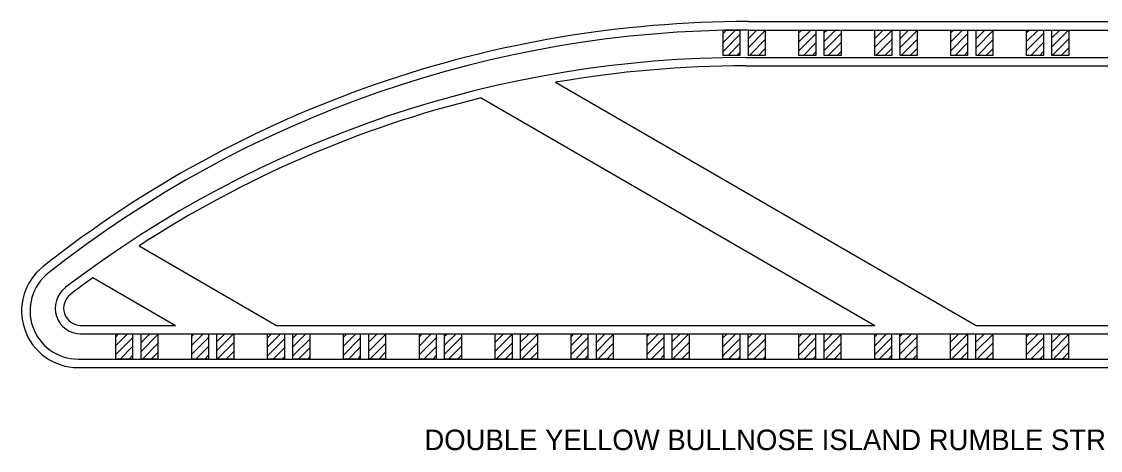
# Model space of a CAD drawing. Extents: x 49976.2 to 50021, y 49987.6 to 50011.4.
# Drawn here: x 50005.605 to 50009.802, y 49990.662 to 49992.329 of the extents above; entities that cross this region are included whole.
import ezdxf

# ---------------------------------------------------------------- set-up
doc = ezdxf.new("R2010")
doc.units = 0
doc.layers.add('Level 1', color=7, linetype='Continuous')
doc.layers.add('Level 2', color=7, linetype='Continuous')

msp = doc.modelspace()

# ---------------------------------------------------------------- linework, layer by layer
at = {"layer": 'Level 1'}
for p, q in [((50008.4327, 49992.329), (50010.6628, 49992.329)), ((50008.3343, 49992.1978), (50008.3343, 49992.2962)), ((50008.3343, 49992.2962), (50008.3999, 49992.2962)), ((50008.3343, 49992.248), (50008.3825, 49992.2962)), ((50008.3343, 49992.2828), (50008.3477, 49992.2962)), ((50008.3343, 49992.2132), (50008.3999, 49992.2789)), ((50008.3999, 49992.2962), (50008.3999, 49992.1978)), ((50008.4327, 49992.2962), (50010.6628, 49992.2962)), ((50008.4327, 49992.1978), (50008.4327, 49992.2962)), ((50008.4327, 49992.2962), (50008.4983, 49992.2962)), ((50008.4327, 49992.2631), (50008.4658, 49992.2962)), ((50008.4327, 49992.2283), (50008.4983, 49992.2939)), ((50008.4983, 49992.2962), (50008.4983, 49992.1978)), ((50008.6296, 49992.1978), (50008.6296, 49992.2962)), ((50008.6296, 49992.2962), (50008.6952, 49992.2962)), ((50008.6296, 49992.25), (50008.6757, 49992.2962)), ((50008.6296, 49992.2848), (50008.6409, 49992.2962)), ((50008.6296, 49992.2152), (50008.6952, 49992.2808)), ((50008.6952, 49992.2962), (50008.6952, 49992.1978)), ((50008.728, 49992.1978), (50008.728, 49992.2962)), ((50008.728, 49992.2962), (50008.7936, 49992.2962)), ((50008.728, 49992.2519), (50008.7723, 49992.2962)), ((50008.728, 49992.2867), (50008.7375, 49992.2962)), ((50008.728, 49992.2171), (50008.7936, 49992.2827)), ((50008.7936, 49992.2962), (50008.7936, 49992.1978)), ((50008.9248, 49992.1978), (50008.9248, 49992.2962)), ((50008.9248, 49992.2962), (50008.9904, 49992.2962)), ((50008.9248, 49992.2638), (50008.9573, 49992.2962)), ((50008.9248, 49992.229), (50008.9904, 49992.2946)), ((50008.9904, 49992.2962), (50008.9904, 49992.1978)), ((50009.0232, 49992.1978), (50009.0232, 49992.2962)), ((50009.0232, 49992.2962), (50009.0888, 49992.2962)), ((50009.0232, 49992.2632), (50009.0563, 49992.2962)), ((50009.0232, 49992.2284), (50009.0888, 49992.294)), ((50009.0888, 49992.2962), (50009.0888, 49992.1978)), ((50009.22, 49992.1978), (50009.22, 49992.2962)), ((50009.22, 49992.2962), (50009.2857, 49992.2962)), ((50009.22, 49992.2503), (50009.2659, 49992.2962)), ((50009.22, 49992.2851), (50009.2312, 49992.2962)), ((50009.22, 49992.2155), (50009.2857, 49992.2811)), ((50009.2857, 49992.2962), (50009.2857, 49992.1978)), ((50009.3185, 49992.1978), (50009.3185, 49992.2962)), ((50009.3185, 49992.2962), (50009.3841, 49992.2962)), ((50009.3185, 49992.2623), (50009.3524, 49992.2962)), ((50009.3185, 49992.2275), (50009.3841, 49992.2931)), ((50009.3841, 49992.2962), (50009.3841, 49992.1978)), ((50009.5153, 49992.1978), (50009.5153, 49992.2962)), ((50009.5153, 49992.2962), (50009.5809, 49992.2962)), ((50009.5153, 49992.2515), (50009.56, 49992.2962)), ((50009.5153, 49992.2863), (50009.5252, 49992.2962)), ((50009.5153, 49992.2167), (50009.5809, 49992.2823)), ((50009.5809, 49992.2962), (50009.5809, 49992.1978)), ((50009.6137, 49992.1978), (50009.6137, 49992.2962)), ((50009.6137, 49992.2962), (50009.6793, 49992.2962)), ((50009.6137, 49992.2314), (50009.6786, 49992.2962)), ((50009.6137, 49992.2661), (50009.6438, 49992.2962)), ((50009.6793, 49992.2962), (50009.6793, 49992.1978)), ((50008.3537, 49992.1978), (50008.3999, 49992.2441)), ((50008.437, 49992.1978), (50008.4983, 49992.2591)), ((50008.6469, 49992.1978), (50008.6952, 49992.246)), ((50008.7434, 49992.1978), (50008.7936, 49992.2479)), ((50008.9284, 49992.1978), (50008.9904, 49992.2598)), ((50009.0274, 49992.1978), (50009.0888, 49992.2592)), ((50009.2371, 49992.1978), (50009.2857, 49992.2463)), ((50009.3236, 49992.1978), (50009.3841, 49992.2583)), ((50009.5312, 49992.1978), (50009.5809, 49992.2475)), ((50009.6149, 49992.1978), (50009.6793, 49992.2622)), ((50008.3999, 49992.1978), (50008.3343, 49992.1978)), ((50008.3885, 49992.1978), (50008.3999, 49992.2093)), ((50008.4983, 49992.1978), (50008.4327, 49992.1978)), ((50008.4718, 49992.1978), (50008.4983, 49992.2243)), ((50008.6952, 49992.1978), (50008.6296, 49992.1978)), ((50008.6817, 49992.1978), (50008.6952, 49992.2113)), ((50008.7936, 49992.1978), (50008.728, 49992.1978)), ((50008.7782, 49992.1978), (50008.7936, 49992.2131)), ((50008.9904, 49992.1978), (50008.9248, 49992.1978)), ((50008.9632, 49992.1978), (50008.9904, 49992.225)), ((50009.0888, 49992.1978), (50009.0232, 49992.1978)), ((50009.0622, 49992.1978), (50009.0888, 49992.2244)), ((50009.2857, 49992.1978), (50009.22, 49992.1978)), ((50009.2719, 49992.1978), (50009.2857, 49992.2115)), ((50009.3841, 49992.1978), (50009.3185, 49992.1978)), ((50009.3583, 49992.1978), (50009.3841, 49992.2235)), ((50009.5809, 49992.1978), (50009.5153, 49992.1978)), ((50009.566, 49992.1978), (50009.5809, 49992.2127)), ((50009.6793, 49992.1978), (50009.6137, 49992.1978)), ((50009.6497, 49992.1978), (50009.6793, 49992.2274)), ((50008.4226, 49992.1895), (50010.6527, 49992.1895)), ((50008.4226, 49992.1567), (50009.8761, 49992.1567)), ((50007.6822, 49992.0929), (50009.3188, 49991.148)), ((50007.3931, 49992.0325), (50008.9251, 49991.148)), ((50006.0624, 49991.4569), (50006.5974, 49991.148)), ((50005.8826, 49991.3335), (50006.2037, 49991.148)), ((50005.8347, 49991.148), (50006.2037, 49991.148)), ((50006.5974, 49991.148), (50008.9251, 49991.148)), ((50009.3188, 49991.148), (50010.6628, 49991.148)), ((50005.8347, 49991.1152), (50010.6628, 49991.1152)), ((50005.9717, 49991.0168), (50005.9717, 49991.1152)), ((50005.9717, 49991.1152), (50006.0373, 49991.1152)), ((50005.9717, 49991.0693), (50006.0176, 49991.1152)), ((50005.9717, 49991.1041), (50005.9828, 49991.1152)), ((50006.0373, 49991.1152), (50006.0373, 49991.0168)), ((50006.0701, 49991.0168), (50006.0701, 49991.1152)), ((50006.0701, 49991.1152), (50006.1357, 49991.1152)), ((50006.0701, 49991.0813), (50006.104, 49991.1152)), ((50006.0701, 49991.0465), (50006.1357, 49991.1121)), ((50006.1357, 49991.1152), (50006.1357, 49991.0168)), ((50006.267, 49991.0168), (50006.267, 49991.1152)), ((50006.267, 49991.1152), (50006.3326, 49991.1152)), ((50006.267, 49991.0705), (50006.3117, 49991.1152)), ((50006.267, 49991.1053), (50006.2769, 49991.1152)), ((50006.267, 49991.0357), (50006.3326, 49991.1013)), ((50006.3326, 49991.1152), (50006.3326, 49991.0168)), ((50006.3654, 49991.0168), (50006.3654, 49991.1152)), ((50006.3654, 49991.1152), (50006.431, 49991.1152)), ((50006.3654, 49991.0504), (50006.4302, 49991.1152)), ((50006.3654, 49991.0852), (50006.3954, 49991.1152)), ((50006.431, 49991.1152), (50006.431, 49991.0168)), ((50006.5622, 49991.0168), (50006.5622, 49991.1152)), ((50006.5622, 49991.1152), (50006.6278, 49991.1152)), ((50006.5622, 49991.0645), (50006.613, 49991.1152)), ((50006.5622, 49991.0992), (50006.5782, 49991.1152)), ((50006.6278, 49991.1152), (50006.6278, 49991.0168)), ((50006.6606, 49991.0168), (50006.6606, 49991.1152)), ((50006.6606, 49991.1152), (50006.7262, 49991.1152)), ((50006.6606, 49991.0641), (50006.7117, 49991.1152)), ((50006.6606, 49991.0989), (50006.677, 49991.1152)), ((50006.7262, 49991.1152), (50006.7262, 49991.0168)), ((50006.8574, 49991.0168), (50006.8574, 49991.1152)), ((50006.8574, 49991.1152), (50006.9231, 49991.1152)), ((50006.8574, 49991.0671), (50006.9056, 49991.1152)), ((50006.8574, 49991.1019), (50006.8708, 49991.1152)), ((50006.9231, 49991.1152), (50006.9231, 49991.0168)), ((50006.9559, 49991.0168), (50006.9559, 49991.1152)), ((50006.9559, 49991.1152), (50007.0215, 49991.1152)), ((50006.9559, 49991.0821), (50006.989, 49991.1152)), ((50006.9559, 49991.0473), (50007.0215, 49991.1129)), ((50007.0215, 49991.1152), (50007.0215, 49991.0168)), ((50007.1527, 49991.0168), (50007.1527, 49991.1152)), ((50007.1527, 49991.1152), (50007.2183, 49991.1152)), ((50007.1527, 49991.069), (50007.1989, 49991.1152)), ((50007.1527, 49991.1038), (50007.1641, 49991.1152)), ((50007.2183, 49991.1152), (50007.2183, 49991.0168)), ((50007.2511, 49991.0168), (50007.2511, 49991.1152)), ((50007.2511, 49991.1152), (50007.3167, 49991.1152)), ((50007.2511, 49991.0709), (50007.2954, 49991.1152)), ((50007.2511, 49991.1057), (50007.2606, 49991.1152)), ((50007.2511, 49991.0361), (50007.3167, 49991.1018)), ((50007.3167, 49991.1152), (50007.3167, 49991.0168)), ((50007.4479, 49991.0168), (50007.4479, 49991.1152)), ((50007.4479, 49991.1152), (50007.5135, 49991.1152)), ((50007.4479, 49991.0828), (50007.4804, 49991.1152)), ((50007.4479, 49991.048), (50007.5135, 49991.1136)), ((50007.5135, 49991.1152), (50007.5135, 49991.0168)), ((50007.5464, 49991.0168), (50007.5464, 49991.1152)), ((50007.5464, 49991.1152), (50007.612, 49991.1152)), ((50007.5464, 49991.0822), (50007.5794, 49991.1152)), ((50007.5464, 49991.0474), (50007.612, 49991.113)), ((50007.612, 49991.1152), (50007.612, 49991.0168)), ((50007.7432, 49991.0168), (50007.7432, 49991.1152)), ((50007.7432, 49991.1152), (50007.8088, 49991.1152)), ((50007.7432, 49991.0693), (50007.7891, 49991.1152)), ((50007.7432, 49991.1041), (50007.7543, 49991.1152)), ((50007.8088, 49991.1152), (50007.8088, 49991.0168)), ((50007.8416, 49991.0168), (50007.8416, 49991.1152)), ((50007.8416, 49991.1152), (50007.9072, 49991.1152)), ((50007.8416, 49991.0813), (50007.8755, 49991.1152)), ((50007.8416, 49991.0465), (50007.9072, 49991.1121)), ((50007.9072, 49991.1152), (50007.9072, 49991.0168)), ((50008.0384, 49991.0168), (50008.0384, 49991.1152)), ((50008.0384, 49991.1152), (50008.104, 49991.1152)), ((50008.0384, 49991.0705), (50008.0832, 49991.1152)), ((50008.0384, 49991.1053), (50008.0484, 49991.1152)), ((50008.0384, 49991.0357), (50008.104, 49991.1013)), ((50008.104, 49991.1152), (50008.104, 49991.0168)), ((50008.1368, 49991.0168), (50008.1368, 49991.1152)), ((50008.1368, 49991.1152), (50008.2025, 49991.1152)), ((50008.1368, 49991.0504), (50008.2017, 49991.1152)), ((50008.1368, 49991.0852), (50008.1669, 49991.1152)), ((50008.2025, 49991.1152), (50008.2025, 49991.0168)), ((50008.3337, 49991.0168), (50008.3337, 49991.1152)), ((50008.3337, 49991.1152), (50008.3993, 49991.1152)), ((50008.3337, 49991.0645), (50008.3845, 49991.1152)), ((50008.3337, 49991.0992), (50008.3497, 49991.1152)), ((50008.3993, 49991.1152), (50008.3993, 49991.0168)), ((50008.4321, 49991.0168), (50008.4321, 49991.1152)), ((50008.4321, 49991.1152), (50008.4977, 49991.1152)), ((50008.4321, 49991.0641), (50008.4832, 49991.1152)), ((50008.4321, 49991.0989), (50008.4484, 49991.1152)), ((50008.4977, 49991.1152), (50008.4977, 49991.0168)), ((50008.6289, 49991.0168), (50008.6289, 49991.1152)), ((50008.6289, 49991.1152), (50008.6945, 49991.1152)), ((50008.6289, 49991.0671), (50008.6771, 49991.1152)), ((50008.6289, 49991.1019), (50008.6423, 49991.1152)), ((50008.6945, 49991.1152), (50008.6945, 49991.0168)), ((50008.7273, 49991.0168), (50008.7273, 49991.1152)), ((50008.7273, 49991.1152), (50008.7929, 49991.1152)), ((50008.7273, 49991.0821), (50008.7604, 49991.1152)), ((50008.7273, 49991.0473), (50008.7929, 49991.1129)), ((50008.7929, 49991.1152), (50008.7929, 49991.0168)), ((50008.9242, 49991.0168), (50008.9242, 49991.1152)), ((50008.9242, 49991.1152), (50008.9898, 49991.1152)), ((50008.9242, 49991.069), (50008.9703, 49991.1152)), ((50008.9242, 49991.1038), (50008.9356, 49991.1152)), ((50008.9898, 49991.1152), (50008.9898, 49991.0168)), ((50009.0226, 49991.0168), (50009.0226, 49991.1152)), ((50009.0226, 49991.1152), (50009.0882, 49991.1152)), ((50009.0226, 49991.0709), (50009.0669, 49991.1152)), ((50009.0226, 49991.1057), (50009.0321, 49991.1152)), ((50009.0226, 49991.0361), (50009.0882, 49991.1018)), ((50009.0882, 49991.1152), (50009.0882, 49991.0168)), ((50009.2194, 49991.0168), (50009.2194, 49991.1152)), ((50009.2194, 49991.1152), (50009.285, 49991.1152)), ((50009.2194, 49991.0828), (50009.2519, 49991.1152)), ((50009.2194, 49991.048), (50009.285, 49991.1136)), ((50009.285, 49991.1152), (50009.285, 49991.0168)), ((50009.3178, 49991.0168), (50009.3178, 49991.1152)), ((50009.3178, 49991.1152), (50009.3834, 49991.1152)), ((50009.3178, 49991.0822), (50009.3509, 49991.1152)), ((50009.3178, 49991.0474), (50009.3834, 49991.113)), ((50009.3834, 49991.1152), (50009.3834, 49991.0168)), ((50009.5147, 49991.0168), (50009.5147, 49991.1152)), ((50009.5147, 49991.1152), (50009.5803, 49991.1152)), ((50009.5147, 49991.0693), (50009.5606, 49991.1152)), ((50009.5147, 49991.1041), (50009.5258, 49991.1152)), ((50009.5803, 49991.1152), (50009.5803, 49991.0168)), ((50009.6131, 49991.0168), (50009.6131, 49991.1152)), ((50009.6131, 49991.1152), (50009.6787, 49991.1152)), ((50009.6131, 49991.0813), (50009.647, 49991.1152)), ((50009.6131, 49991.0465), (50009.6787, 49991.1121)), ((50009.6787, 49991.1152), (50009.6787, 49991.0168)), ((50005.9717, 49991.0345), (50006.0373, 49991.1001)), ((50005.9888, 49991.0168), (50006.0373, 49991.0654)), ((50006.0752, 49991.0168), (50006.1357, 49991.0773)), ((50006.2829, 49991.0168), (50006.3326, 49991.0665)), ((50006.3666, 49991.0168), (50006.431, 49991.0812)), ((50006.5622, 49991.0297), (50006.6278, 49991.0953)), ((50006.5842, 49991.0168), (50006.6278, 49991.0605)), ((50006.6606, 49991.0293), (50006.7262, 49991.0949)), ((50006.6829, 49991.0168), (50006.7262, 49991.0601)), ((50006.8574, 49991.0323), (50006.9231, 49991.0979)), ((50006.8768, 49991.0168), (50006.9231, 49991.0631)), ((50006.9601, 49991.0168), (50007.0215, 49991.0781)), ((50007.1527, 49991.0343), (50007.2183, 49991.0999)), ((50007.1701, 49991.0168), (50007.2183, 49991.0651)), ((50007.2666, 49991.0168), (50007.3167, 49991.067)), ((50007.4516, 49991.0168), (50007.5135, 49991.0788)), ((50007.5506, 49991.0168), (50007.612, 49991.0782)), ((50007.7432, 49991.0345), (50007.8088, 49991.1001)), ((50007.7603, 49991.0168), (50007.8088, 49991.0654)), ((50007.8467, 49991.0168), (50007.9072, 49991.0773)), ((50008.0543, 49991.0168), (50008.104, 49991.0665)), ((50008.1381, 49991.0168), (50008.2025, 49991.0812)), ((50008.3337, 49991.0297), (50008.3993, 49991.0953)), ((50008.3556, 49991.0168), (50008.3993, 49991.0605)), ((50008.4321, 49991.0293), (50008.4977, 49991.0949)), ((50008.4544, 49991.0168), (50008.4977, 49991.0601)), ((50008.6289, 49991.0323), (50008.6945, 49991.0979)), ((50008.6483, 49991.0168), (50008.6945, 49991.0631)), ((50008.7316, 49991.0168), (50008.7929, 49991.0781)), ((50008.9242, 49991.0343), (50008.9898, 49991.0999)), ((50008.9415, 49991.0168), (50008.9898, 49991.0651)), ((50009.038, 49991.0168), (50009.0882, 49991.067)), ((50009.223, 49991.0168), (50009.285, 49991.0788)), ((50009.322, 49991.0168), (50009.3834, 49991.0782)), ((50009.5147, 49991.0345), (50009.5803, 49991.1001)), ((50009.5317, 49991.0168), (50009.5803, 49991.0654)), ((50009.6182, 49991.0168), (50009.6787, 49991.0773)), ((50005.8253, 49991.0168), (50010.6628, 49991.0168)), ((50006.0373, 49991.0168), (50005.9717, 49991.0168)), ((50006.0236, 49991.0168), (50006.0373, 49991.0306)), ((50006.1357, 49991.0168), (50006.0701, 49991.0168)), ((50006.11, 49991.0168), (50006.1357, 49991.0425)), ((50006.3326, 49991.0168), (50006.267, 49991.0168)), ((50006.3177, 49991.0168), (50006.3326, 49991.0317)), ((50006.431, 49991.0168), (50006.3654, 49991.0168)), ((50006.4014, 49991.0168), (50006.431, 49991.0464)), ((50006.6278, 49991.0168), (50006.5622, 49991.0168)), ((50006.619, 49991.0168), (50006.6278, 49991.0257)), ((50006.7262, 49991.0168), (50006.6606, 49991.0168)), ((50006.7177, 49991.0168), (50006.7262, 49991.0253)), ((50006.9231, 49991.0168), (50006.8574, 49991.0168)), ((50006.9116, 49991.0168), (50006.9231, 49991.0283)), ((50007.0215, 49991.0168), (50006.9559, 49991.0168)), ((50006.9949, 49991.0168), (50007.0215, 49991.0434)), ((50007.2183, 49991.0168), (50007.1527, 49991.0168)), ((50007.2048, 49991.0168), (50007.2183, 49991.0303)), ((50007.3167, 49991.0168), (50007.2511, 49991.0168)), ((50007.3014, 49991.0168), (50007.3167, 49991.0322)), ((50007.5135, 49991.0168), (50007.4479, 49991.0168)), ((50007.4864, 49991.0168), (50007.5135, 49991.044)), ((50007.612, 49991.0168), (50007.5464, 49991.0168)), ((50007.5854, 49991.0168), (50007.612, 49991.0434)), ((50007.8088, 49991.0168), (50007.7432, 49991.0168)), ((50007.7951, 49991.0168), (50007.8088, 49991.0306)), ((50007.9072, 49991.0168), (50007.8416, 49991.0168)), ((50007.8815, 49991.0168), (50007.9072, 49991.0425)), ((50008.104, 49991.0168), (50008.0384, 49991.0168)), ((50008.0891, 49991.0168), (50008.104, 49991.0317)), ((50008.2025, 49991.0168), (50008.1368, 49991.0168)), ((50008.1729, 49991.0168), (50008.2025, 49991.0464)), ((50008.3993, 49991.0168), (50008.3337, 49991.0168)), ((50008.3904, 49991.0168), (50008.3993, 49991.0257)), ((50008.4977, 49991.0168), (50008.4321, 49991.0168)), ((50008.4892, 49991.0168), (50008.4977, 49991.0253)), ((50008.6945, 49991.0168), (50008.6289, 49991.0168)), ((50008.6831, 49991.0168), (50008.6945, 49991.0283)), ((50008.7929, 49991.0168), (50008.7273, 49991.0168)), ((50008.7664, 49991.0168), (50008.7929, 49991.0434)), ((50008.9898, 49991.0168), (50008.9242, 49991.0168)), ((50008.9763, 49991.0168), (50008.9898, 49991.0303)), ((50009.0882, 49991.0168), (50009.0226, 49991.0168)), ((50009.0728, 49991.0168), (50009.0882, 49991.0322)), ((50009.285, 49991.0168), (50009.2194, 49991.0168)), ((50009.2578, 49991.0168), (50009.285, 49991.044)), ((50009.3834, 49991.0168), (50009.3178, 49991.0168)), ((50009.3568, 49991.0168), (50009.3834, 49991.0434)), ((50009.5803, 49991.0168), (50009.5147, 49991.0168)), ((50009.5665, 49991.0168), (50009.5803, 49991.0306)), ((50009.6787, 49991.0168), (50009.6131, 49991.0168)), ((50009.653, 49991.0168), (50009.6787, 49991.0425)), ((50005.8253, 49990.984), (50010.6628, 49990.984))]:
    msp.add_line(p, q, dxfattribs=at)
for centre, radius, start, end in [((50008.4327, 49987.9003), 4.4287, 90, 128.2824), ((50008.4327, 49987.9003), 4.3959, 90, 128.2824), ((50008.4226, 49987.8264), 4.3631, 90, 127.3522), ((50008.4226, 49987.8264), 4.3303, 90, 99.8455), ((50008.4226, 49987.8264), 4.3303, 103.7536, 123.0287), ((50005.8253, 49991.204), 0.22, 128.2824, 270), ((50005.8253, 49991.204), 0.1872, 128.2824, 270), ((50008.4226, 49987.8264), 4.3303, 125.9152, 127.3522), ((50005.8362, 49991.2152), 0.1, 127.3522, 270), ((50005.8362, 49991.2152), 0.0672, 127.3522, 270)]:
    msp.add_arc(centre, radius, start, end, dxfattribs=at)

# ---------------------------------------------------------------- texts
at = {"layer": 'Level 2'}
msp.add_text('DOUBLE YELLOW BULLNOSE ISLAND RUMBLE STRIPE', height=0.08, dxfattribs=at).set_placement((50007.1723, 49990.663))

doc.saveas('drawing.dxf')
